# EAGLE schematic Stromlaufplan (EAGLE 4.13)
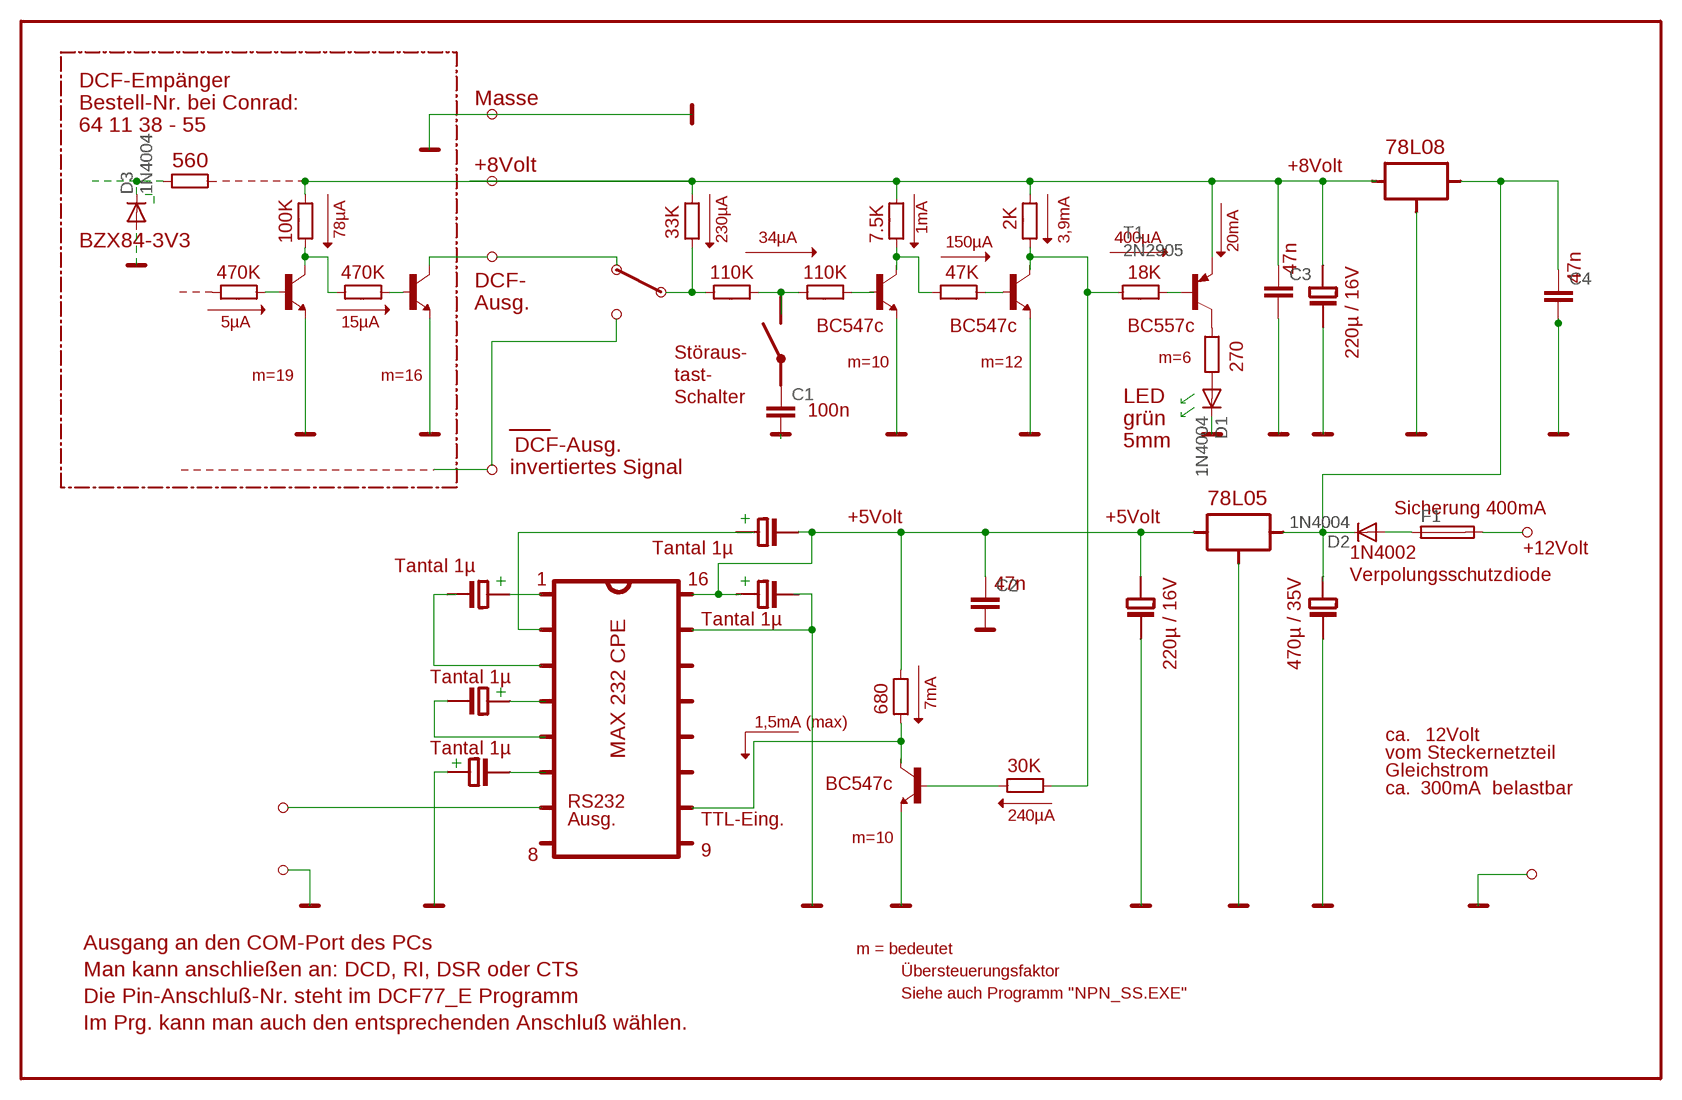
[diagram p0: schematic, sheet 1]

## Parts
C1  C2,5-3  [C2.5-3]
C2  C2,5-3  [C2.5-3]
C3  C2,5-3  [C2.5-3]
C4  C2,5-3  [C2.5-3]
D1  1N4004  [DO41-10]
D2  1N4004  [DO41-10]
D3  1N4004  [DO41-10]
F1  19559  [19559]
T1  2N2905  [TO5]

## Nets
N$7: C3.1 T1.1(E)
N$11: D1.C
N$12: T1.2(B)
N$18: C1.2
N$21: C2.1
N$41: C4.1 D2.C
N$42: D2.A F1.1
N$43: F1.2
N$45: D3.C
N$57: D3.A
N$59: C3.2
N$62: C4.2
Unconnected: C1.1 C2.2 D1.A T1.3(C)

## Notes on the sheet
- DCF-Empänger
- Bestell-Nr. bei Conrad: | Masse
- 64 11 38 - 55
- 78L08
- 560 | +8Volt | +8Volt
- 1mA | 2K
- 100K | 78µA | 33K | 230µA | 34µA | 7.5K | 3,9mA | 400µA
- BZX84-3V3 | 150µA | 20mA
- 470K | 470K | 110K | 110K | 47K | 18K | 47n
- DCF- | 47n
- Ausg.
- 5µA | 15µA | BC547c | BC547c | BC557c
- Störaus- | m=6 | 220µ / 16V
- m=10 | m=12 | 270
- m=19 | m=16 | tast-
- Schalter | LED
- 100n
- grün
- DCF-Ausg. | 5mm
- invertiertes Signal
- 78L05
- Sicherung 400mA
- +5Volt | +5Volt
- Tantal 1µ | 1N4002 | +12Volt
- Tantal 1µ
- 1 | 16 | Verpolungsschutzdiode
- 47n
- Tantal 1µ
- 220µ / 16V | 470µ / 35V
- Tantal 1µ
- 680 | 7mA
- 1,5mA (max)
- ca. | 12Volt
- Tantal 1µ | MAX 232 CPE | vom Steckernetzteil
- 30K | Gleichstrom
- BC547c | ca. | 300mA | belastbar
- RS232
- Ausg. | TTL-Eing. | 240µA
- m=10
- 8 | 9
- Ausgang an den COM-Port des PCs | m = bedeutet
- Man kann anschließen an: DCD, RI, DSR oder CTS | Übersteuerungsfaktor
- Die Pin-Anschluß-Nr. steht im DCF77_E Programm | Siehe auch Programm "NPN_SS.EXE"
- Im Prg. kann man auch den entsprechenden Anschluß wählen.

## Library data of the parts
C1-C4 = capacitor-wima:C: CAPACITOR
D1-D3 = diode:1N4004: DIODE
F1 = fuse:19559: FUSE HOLDER
T1 = transistor-pnp:2N2905: PNP Transistor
